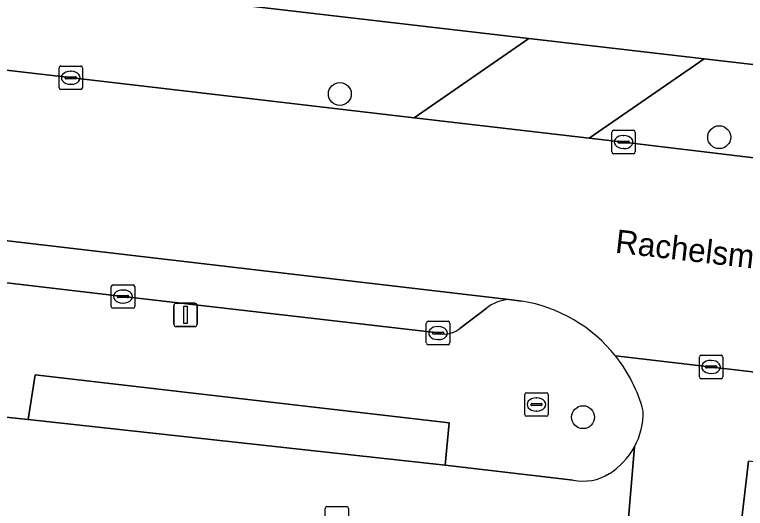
# Model space of a CAD drawing. Extents: x 161241 to 161758, y 384138 to 384885.
# Drawn here: x 161368.75 to 161399.95, y 384644.39 to 384665.48 of the extents above; entities that cross this region are included whole.
import ezdxf

# ---------------------------------------------------------------- set-up
doc = ezdxf.new("R2010")
doc.units = 0
for name, color, linetype in [('IMGEO_Boom', 7, 'Continuous'), ('IMGEO_Brandkraan', 7, 'Continuous'), ('IMGEO_Erf', 7, 'Continuous'), ('IMGEO_Groenvoorziening', 7, 'Continuous'), ('IMGEO_Kolk', 7, 'Continuous'), ('IMGEO_Lichtmast', 7, 'Continuous'), ('IMGEO_Openbare_ruimte_label', 7, 'Continuous'), ('IMGEO_Parkeervlak_open', 7, 'Continuous'), ('IMGEO_Rijbaan_lokaal_gesloten', 7, 'Continuous'), ('IMGEO_Rijbaan_lokaal_open', 7, 'Continuous'), ('IMGEO_Voetpad_open', 7, 'Continuous')]:
    doc.layers.add(name, color=color, linetype=linetype)

msp = doc.modelspace()

# ---------------------------------------------------------------- linework, layer by layer
at = {"layer": 'IMGEO_Boom'}
for centre in [(161382.634, 384662.092), (161398.831, 384660.245), (161393.019, 384648.288)]:
    msp.add_circle(centre, 0.489, dxfattribs=at)
at = {"layer": 'IMGEO_Brandkraan'}
for p, q in [((161390.603, 384649.33), (161391.455, 384649.33)), ((161390.528, 384648.404), (161390.528, 384649.256)), ((161391.016, 384649.11), (161391.041, 384649.11)), ((161391.529, 384649.256), (161391.529, 384648.404)), ((161390.787, 384648.824), (161390.787, 384648.836)), ((161391.225, 384648.787), (161390.827, 384648.787)), ((161390.83, 384648.873), (161391.228, 384648.873)), ((161391.271, 384648.836), (161391.271, 384648.824)), ((161391.039, 384648.55), (161391.014, 384648.55)), ((161391.455, 384648.33), (161390.603, 384648.33))]:
    msp.add_line(p, q, dxfattribs=at)
for points in [[(161390.603, 384649.33), (161391.455, 384649.33)], [(161390.528, 384648.404), (161390.528, 384649.256)], [(161391.529, 384649.256), (161391.529, 384648.404)], [(161391.455, 384648.33), (161390.603, 384648.33)]]:
    msp.add_lwpolyline(points, dxfattribs=at)
for centre, radius, start, end in [((161390.605, 384649.254), 0.0765, 91.552, 178.448), ((161390.605, 384649.254), 0.0765, 91.552, 178.448), ((161391.453, 384649.254), 0.0765, 1.552, 88.448), ((161391.453, 384649.254), 0.0765, 1.552, 88.448), ((161390.827, 384648.833), 0.0403, 85.8775, 175.7526), ((161390.824, 384648.823), 0.0366, 178.938, 274.7102), ((161391.228, 384648.83), 0.043, 264.8664, 352.4533), ((161391.232, 384648.835), 0.0386, 1.7309, 96.639), ((161390.605, 384648.406), 0.0765, 181.552, 268.448), ((161390.605, 384648.406), 0.0765, 181.552, 268.448), ((161391.453, 384648.406), 0.0765, 271.552, 358.448), ((161391.453, 384648.406), 0.0765, 271.552, 358.448)]:
    msp.add_arc(centre, radius, start, end, dxfattribs=at)
for centre, major_axis, ratio, start_param, end_param in [((161391.015, 384648.83), (-0.387, 0.002), 0.722429, 4.712389, 7.853982), ((161391.04, 384648.83), (-0.39, 0.002), 0.717154, 1.570796, 4.712389)]:
    msp.add_ellipse(centre, major_axis=major_axis, ratio=ratio, start_param=start_param, end_param=end_param, dxfattribs=at)
at = {"layer": 'IMGEO_Erf'}
for points in [[(161377.488, 384665.995), (161390.698, 384664.458), (161398.187, 384663.587), (161492.983, 384652.558), (161493.77, 384652.466), (161499.707, 384651.762), (161500, 384651.728), (161502.244, 384651.462), (161505.627, 384651.061), (161514.982, 384650.128), (161514.74, 384648.343), (161518.212, 384647.951), (161518.142, 384647.334), (161519.881, 384647.123), (161519.952, 384647.742), (161538.83, 384645.535)], [(161458.589, 384639.718), (161400.088, 384646.416), (161397.281, 384622.401), (161396.961, 384619.66), (161396.655, 384617.039), (161425.024, 384613.724), (161425.387, 384616.773), (161427.698, 384616.498), (161427.335, 384613.449), (161436.939, 384612.308), (161436.503, 384609.048), (161435.624, 384602.469), (161435.067, 384598.3), (161434.079, 384598.432), (161434.571, 384602.594), (161430.726, 384603.048), (161431.421, 384608.981), (161396.194, 384613.099), (161395.453, 384606.759), (161397.13, 384605.671), (161394.834, 384585.76), (161392.961, 384585.251), (161392.905, 384584.764)]]:
    msp.add_lwpolyline(points, dxfattribs=at)
at = {"layer": 'IMGEO_Groenvoorziening'}
for points in [[(161373.378, 384653.44), (161350.975, 384656.07), (161350.318, 384656.437), (161349.675, 384657.343)], [(161336.327, 384651.975), (161339.683, 384651.538), (161339.996, 384654.506), (161344.076, 384654.055), (161343.965, 384653.098), (161347.266, 384652.698), (161357.636, 384651.397), (161357.522, 384649.433), (161369.332, 384648.189), (161369.629, 384650.1), (161387.303, 384648.045), (161387.138, 384646.243), (161392.599, 384645.601)], [(161386.991, 384651.842), (161386.828, 384651.884), (161373.378, 384653.44)], [(161390.409, 384653.248), (161389.854, 384653.313)], [(161388.883, 384652.935), (161387.754, 384652.082)]]:
    msp.add_lwpolyline(points, dxfattribs=at)
for centre, radius, start, end in [((161389.941, 384651.653), 1.662, 93.0057, 129.5352), ((161389.365, 384646.891), 6.442, 38.5747, 80.67), ((161387.088, 384652.868), 1.03, 264.6158, 310.3059), ((161389.322, 384646.875), 6.486, 14.9877, 38.4532), ((161392.483, 384648.507), 3.105, 331.4579, 0.8228), ((161392.478, 384648.51), 3.11, 302.1487, 331.4569), ((161393.024, 384647.638), 2.081, 258.2077, 302.1915)]:
    msp.add_arc(centre, radius, start, end, dxfattribs=at)
at = {"layer": 'IMGEO_Kolk'}
for p, q in [((161370.645, 384662.36), (161370.645, 384663.212)), ((161370.72, 384663.286), (161371.572, 384663.286)), ((161371.133, 384663.066), (161371.158, 384663.066)), ((161371.646, 384663.212), (161371.646, 384662.36)), ((161370.904, 384662.78), (161370.904, 384662.792)), ((161371.342, 384662.743), (161370.944, 384662.743)), ((161370.947, 384662.829), (161371.345, 384662.829)), ((161371.388, 384662.792), (161371.388, 384662.78)), ((161371.156, 384662.506), (161371.131, 384662.506)), ((161371.572, 384662.286), (161370.72, 384662.286)), ((161394.322, 384660.54), (161395.174, 384660.54)), ((161394.247, 384659.614), (161394.247, 384660.466)), ((161394.735, 384660.32), (161394.76, 384660.32)), ((161395.248, 384660.466), (161395.248, 384659.614)), ((161394.506, 384660.034), (161394.506, 384660.046)), ((161394.944, 384659.997), (161394.546, 384659.997)), ((161394.549, 384660.083), (161394.947, 384660.083)), ((161394.99, 384660.046), (161394.99, 384660.034)), ((161394.758, 384659.76), (161394.733, 384659.76)), ((161395.174, 384659.54), (161394.322, 384659.54)), ((161372.877, 384653.014), (161372.877, 384653.866)), ((161372.952, 384653.94), (161373.804, 384653.94)), ((161373.365, 384653.72), (161373.39, 384653.72)), ((161373.878, 384653.866), (161373.878, 384653.014)), ((161373.136, 384653.434), (161373.136, 384653.446)), ((161373.574, 384653.397), (161373.176, 384653.397)), ((161373.179, 384653.483), (161373.577, 384653.483)), ((161373.62, 384653.446), (161373.62, 384653.434)), ((161373.388, 384653.16), (161373.363, 384653.16)), ((161373.804, 384652.94), (161372.952, 384652.94)), ((161386.327, 384651.457), (161386.327, 384652.309)), ((161386.402, 384652.383), (161387.254, 384652.383)), ((161386.815, 384652.163), (161386.84, 384652.163)), ((161387.328, 384652.309), (161387.328, 384651.457)), ((161386.586, 384651.877), (161386.586, 384651.889)), ((161387.024, 384651.84), (161386.626, 384651.84)), ((161386.629, 384651.926), (161387.027, 384651.926)), ((161387.07, 384651.889), (161387.07, 384651.877)), ((161386.838, 384651.603), (161386.813, 384651.603)), ((161387.254, 384651.383), (161386.402, 384651.383)), ((161398.058, 384650.933), (161398.91, 384650.933)), ((161397.983, 384650.007), (161397.983, 384650.859)), ((161398.471, 384650.713), (161398.496, 384650.713)), ((161398.984, 384650.859), (161398.984, 384650.007)), ((161398.242, 384650.427), (161398.242, 384650.439)), ((161398.68, 384650.39), (161398.282, 384650.39)), ((161398.285, 384650.476), (161398.683, 384650.476)), ((161398.726, 384650.439), (161398.726, 384650.427)), ((161398.91, 384649.933), (161398.058, 384649.933)), ((161398.494, 384650.153), (161398.469, 384650.153)), ((161382.008, 384643.542), (161382.008, 384644.394)), ((161382.083, 384644.468), (161382.935, 384644.468)), ((161383.009, 384644.394), (161383.009, 384643.542))]:
    msp.add_line(p, q, dxfattribs=at)
for points in [[(161370.645, 384662.36), (161370.645, 384663.212)], [(161370.72, 384663.286), (161371.572, 384663.286)], [(161371.646, 384663.212), (161371.646, 384662.36)], [(161371.572, 384662.286), (161370.72, 384662.286)], [(161394.322, 384660.54), (161395.174, 384660.54)], [(161394.247, 384659.614), (161394.247, 384660.466)], [(161395.248, 384660.466), (161395.248, 384659.614)], [(161395.174, 384659.54), (161394.322, 384659.54)], [(161372.877, 384653.014), (161372.877, 384653.866)], [(161372.952, 384653.94), (161373.804, 384653.94)], [(161373.878, 384653.866), (161373.878, 384653.014)], [(161373.804, 384652.94), (161372.952, 384652.94)], [(161386.327, 384651.457), (161386.327, 384652.309)], [(161386.402, 384652.383), (161387.254, 384652.383)], [(161387.328, 384652.309), (161387.328, 384651.457)], [(161387.254, 384651.383), (161386.402, 384651.383)], [(161398.058, 384650.933), (161398.91, 384650.933)], [(161397.983, 384650.007), (161397.983, 384650.859)], [(161398.984, 384650.859), (161398.984, 384650.007)], [(161398.91, 384649.933), (161398.058, 384649.933)], [(161382.008, 384643.542), (161382.008, 384644.394)], [(161382.083, 384644.468), (161382.935, 384644.468)], [(161383.009, 384644.394), (161383.009, 384643.542)]]:
    msp.add_lwpolyline(points, dxfattribs=at)
for centre, radius, start, end in [((161370.722, 384663.21), 0.0765, 91.552, 178.448), ((161370.722, 384663.21), 0.0765, 91.552, 178.448), ((161371.57, 384663.21), 0.0765, 1.552, 88.448), ((161371.57, 384663.21), 0.0765, 1.552, 88.448), ((161370.944, 384662.789), 0.0403, 85.8775, 175.7526), ((161370.941, 384662.779), 0.0366, 178.938, 274.7102), ((161371.345, 384662.786), 0.043, 264.8664, 352.4533), ((161371.349, 384662.791), 0.0386, 1.7309, 96.639), ((161370.722, 384662.362), 0.0765, 181.552, 268.448), ((161370.722, 384662.362), 0.0765, 181.552, 268.448), ((161371.57, 384662.362), 0.0765, 271.552, 358.448), ((161371.57, 384662.362), 0.0765, 271.552, 358.448), ((161394.324, 384660.464), 0.0765, 91.552, 178.448), ((161394.324, 384660.464), 0.0765, 91.552, 178.448), ((161395.172, 384660.464), 0.0765, 1.552, 88.448), ((161395.172, 384660.464), 0.0765, 1.552, 88.448), ((161394.546, 384660.043), 0.0403, 85.8775, 175.7526), ((161394.543, 384660.033), 0.0366, 178.938, 274.7102), ((161394.947, 384660.04), 0.043, 264.8664, 352.4533), ((161394.951, 384660.045), 0.0386, 1.7309, 96.639), ((161394.324, 384659.616), 0.0765, 181.552, 268.448), ((161394.324, 384659.616), 0.0765, 181.552, 268.448), ((161395.172, 384659.616), 0.0765, 271.552, 358.448), ((161395.172, 384659.616), 0.0765, 271.552, 358.448), ((161372.954, 384653.864), 0.0765, 91.552, 178.448), ((161372.954, 384653.864), 0.0765, 91.552, 178.448), ((161373.802, 384653.864), 0.0765, 1.552, 88.448), ((161373.802, 384653.864), 0.0765, 1.552, 88.448), ((161373.176, 384653.443), 0.0403, 85.8775, 175.7526), ((161373.173, 384653.433), 0.0366, 178.938, 274.7102), ((161373.577, 384653.44), 0.043, 264.8664, 352.4533), ((161373.581, 384653.445), 0.0386, 1.7309, 96.639), ((161372.954, 384653.016), 0.0765, 181.552, 268.448), ((161372.954, 384653.016), 0.0765, 181.552, 268.448), ((161373.802, 384653.016), 0.0765, 271.552, 358.448), ((161373.802, 384653.016), 0.0765, 271.552, 358.448), ((161386.404, 384652.307), 0.0765, 91.552, 178.448), ((161386.404, 384652.307), 0.0765, 91.552, 178.448), ((161387.252, 384652.307), 0.0765, 1.552, 88.448), ((161387.252, 384652.307), 0.0765, 1.552, 88.448), ((161386.626, 384651.886), 0.0403, 85.8775, 175.7526), ((161386.623, 384651.876), 0.0366, 178.938, 274.7102), ((161387.027, 384651.883), 0.043, 264.8664, 352.4533), ((161387.031, 384651.888), 0.0386, 1.7309, 96.639), ((161386.404, 384651.459), 0.0765, 181.552, 268.448), ((161386.404, 384651.459), 0.0765, 181.552, 268.448), ((161387.252, 384651.459), 0.0765, 271.552, 358.448), ((161387.252, 384651.459), 0.0765, 271.552, 358.448), ((161398.06, 384650.857), 0.0765, 91.552, 178.448), ((161398.06, 384650.857), 0.0765, 91.552, 178.448), ((161398.908, 384650.857), 0.0765, 1.552, 88.448), ((161398.908, 384650.857), 0.0765, 1.552, 88.448), ((161398.282, 384650.436), 0.0403, 85.8775, 175.7526), ((161398.279, 384650.426), 0.0366, 178.938, 274.7102), ((161398.683, 384650.433), 0.043, 264.8664, 352.4533), ((161398.687, 384650.438), 0.0386, 1.7309, 96.639), ((161398.06, 384650.009), 0.0765, 181.552, 268.448), ((161398.06, 384650.009), 0.0765, 181.552, 268.448), ((161398.908, 384650.009), 0.0765, 271.552, 358.448), ((161398.908, 384650.009), 0.0765, 271.552, 358.448), ((161382.085, 384644.392), 0.0765, 91.552, 178.448), ((161382.085, 384644.392), 0.0765, 91.552, 178.448), ((161382.933, 384644.392), 0.0765, 1.552, 88.448), ((161382.933, 384644.392), 0.0765, 1.552, 88.448)]:
    msp.add_arc(centre, radius, start, end, dxfattribs=at)
for centre, major_axis, ratio, start_param, end_param in [((161371.132, 384662.786), (-0.387, 0.002), 0.722429, 4.712389, 7.853982), ((161371.157, 384662.786), (-0.39, 0.002), 0.717154, 1.570796, 4.712389), ((161394.734, 384660.04), (-0.387, 0.002), 0.722429, 4.712389, 7.853982), ((161394.759, 384660.04), (-0.39, 0.002), 0.717154, 1.570796, 4.712389), ((161373.364, 384653.44), (-0.387, 0.002), 0.722429, 4.712389, 7.853982), ((161373.389, 384653.44), (-0.39, 0.002), 0.717154, 1.570796, 4.712389), ((161386.814, 384651.883), (-0.387, 0.002), 0.722429, 4.712389, 7.853982), ((161386.839, 384651.883), (-0.39, 0.002), 0.717154, 1.570796, 4.712389), ((161398.47, 384650.433), (-0.387, 0.002), 0.722429, 4.712389, 7.853982), ((161398.495, 384650.433), (-0.39, 0.002), 0.717154, 1.570796, 4.712389)]:
    msp.add_ellipse(centre, major_axis=major_axis, ratio=ratio, start_param=start_param, end_param=end_param, dxfattribs=at)
at = {"layer": 'IMGEO_Lichtmast'}
for p, q in [((161375.551, 384652.258), (161375.551, 384653.058)), ((161375.551, 384653.058), (161375.551, 384652.258)), ((161375.651, 384653.158), (161376.441, 384653.158)), ((161376.441, 384653.158), (161375.651, 384653.158)), ((161376.541, 384653.058), (161376.541, 384652.258)), ((161376.541, 384652.258), (161376.541, 384653.058)), ((161376.441, 384652.158), (161375.651, 384652.158)), ((161375.651, 384652.158), (161376.441, 384652.158))]:
    msp.add_line(p, q, dxfattribs=at)
msp.add_lwpolyline([(161375.971, 384653.033), (161376.121, 384653.033), (161376.121, 384652.283), (161375.971, 384652.283), (161375.971, 384653.033)], dxfattribs=at)
for centre, start, end in [((161375.651, 384653.058), 90, 180), ((161375.651, 384653.058), 90, 180), ((161376.441, 384653.058), 0, 90), ((161376.441, 384653.058), 360, 90), ((161375.651, 384652.258), 180, 270), ((161375.651, 384652.258), 180, 270), ((161376.441, 384652.258), 270, 0), ((161376.441, 384652.258), 270, 0)]:
    msp.add_arc(centre, 0.1, start, end, dxfattribs=at)
at = {"layer": 'IMGEO_Parkeervlak_open'}
for points in [[(161389.854, 384653.313), (161348.386, 384658.172)], [(161349.675, 384657.343), (161350.318, 384656.437), (161350.975, 384656.07), (161373.378, 384653.44), (161386.828, 384651.884), (161386.991, 384651.842)], [(161387.754, 384652.082), (161388.883, 384652.935)]]:
    msp.add_lwpolyline(points, dxfattribs=at)
msp.add_lwpolyline([(161369.332, 384648.189), (161387.138, 384646.243), (161387.303, 384648.045), (161369.629, 384650.1)], close=True, dxfattribs=at)
for centre, radius, start, end in [((161389.941, 384651.653), 1.662, 93.0057, 129.5352), ((161387.088, 384652.868), 1.03, 264.6158, 310.3059)]:
    msp.add_arc(centre, radius, start, end, dxfattribs=at)
at = {"layer": 'IMGEO_Rijbaan_lokaal_gesloten'}
for points in [[(161323.48, 384667.563), (161318.312, 384668.164), (161316.684, 384668.354), (161316.605, 384668.365), (161313.457, 384668.737), (161313.067, 384668.785), (161312.456, 384662.258), (161313.093, 384662.221), (161315.925, 384661.958), (161316.424, 384661.932), (161317.132, 384661.825), (161329.43, 384660.717), (161330.706, 384660.606), (161331.604, 384660.522), (161342.034, 384658.595), (161348.386, 384658.172), (161389.854, 384653.313), (161390.409, 384653.248)], [(161394.627, 384660.053), (161393.279, 384660.21), (161385.812, 384661.078), (161378.041, 384661.982), (161371.462, 384662.748), (161352.098, 384665), (161346.668, 384665.574), (161337.22, 384666.762), (161335.063, 384667.031)], [(161405.256, 384651.682), (161405.947, 384651.602), (161423.823, 384649.546), (161433.589, 384648.422), (161434.472, 384655.36), (161433.551, 384655.465), (161424.956, 384656.433), (161420.44, 384656.941), (161394.627, 384660.053)], [(161394.401, 384650.908), (161401.463, 384650.085)]]:
    msp.add_lwpolyline(points, dxfattribs=at)
msp.add_arc((161389.365, 384646.891), 6.442, 38.5747, 80.67, dxfattribs=at)
at = {"layer": 'IMGEO_Rijbaan_lokaal_open'}
for points in [[(161369.332, 384648.189), (161357.522, 384649.433), (161344.062, 384651.054), (161339.683, 384651.538), (161336.327, 384651.975)], [(161401.463, 384650.085), (161394.401, 384650.908)], [(161392.599, 384645.601), (161387.138, 384646.243), (161369.332, 384648.189)], [(161395.21, 384647.024), (161394.463, 384638.035), (161392.722, 384622.926), (161397.281, 384622.401), (161400.088, 384646.416)], [(161394.463, 384638.035), (161395.21, 384647.024)]]:
    msp.add_lwpolyline(points, dxfattribs=at)
for centre, radius, start, end in [((161389.322, 384646.875), 6.486, 14.9877, 38.4532), ((161392.483, 384648.507), 3.105, 331.4579, 0.8228), ((161392.478, 384648.51), 3.11, 302.1487, 331.4569), ((161393.024, 384647.638), 2.081, 258.2077, 302.1915)]:
    msp.add_arc(centre, radius, start, end, dxfattribs=at)
at = {"layer": 'IMGEO_Voetpad_open'}
msp.add_lwpolyline([(161335.063, 384667.031), (161337.22, 384666.762), (161346.668, 384665.574), (161352.098, 384665), (161371.462, 384662.748), (161378.041, 384661.982), (161385.812, 384661.078), (161390.698, 384664.458), (161377.488, 384665.995), (161376.893, 384666.064), (161373.854, 384666.414), (161372.409, 384666.581), (161371.982, 384666.631), (161370.695, 384666.781), (161333.364, 384671.12)], dxfattribs=at)
for points in [[(161398.187, 384663.587), (161390.698, 384664.458), (161385.812, 384661.078), (161393.279, 384660.21)], [(161398.187, 384663.587), (161393.279, 384660.21), (161394.627, 384660.053), (161420.44, 384656.941), (161424.956, 384656.433), (161433.551, 384655.465), (161434.472, 384655.36), (161437.269, 384655.04), (161448.451, 384653.761), (161461.074, 384652.254), (161468.593, 384651.357), (161488.024, 384649.043), (161492.527, 384648.513), (161492.983, 384652.558)]]:
    msp.add_lwpolyline(points, close=True, dxfattribs=at)

# ---------------------------------------------------------------- texts
at = {"layer": 'IMGEO_Openbare_ruimte_label'}
msp.add_text('Rachelsmolen', height=1, rotation=353.4509, dxfattribs=at).set_placement((161394.361, 384655.317))

doc.saveas('drawing.dxf')
